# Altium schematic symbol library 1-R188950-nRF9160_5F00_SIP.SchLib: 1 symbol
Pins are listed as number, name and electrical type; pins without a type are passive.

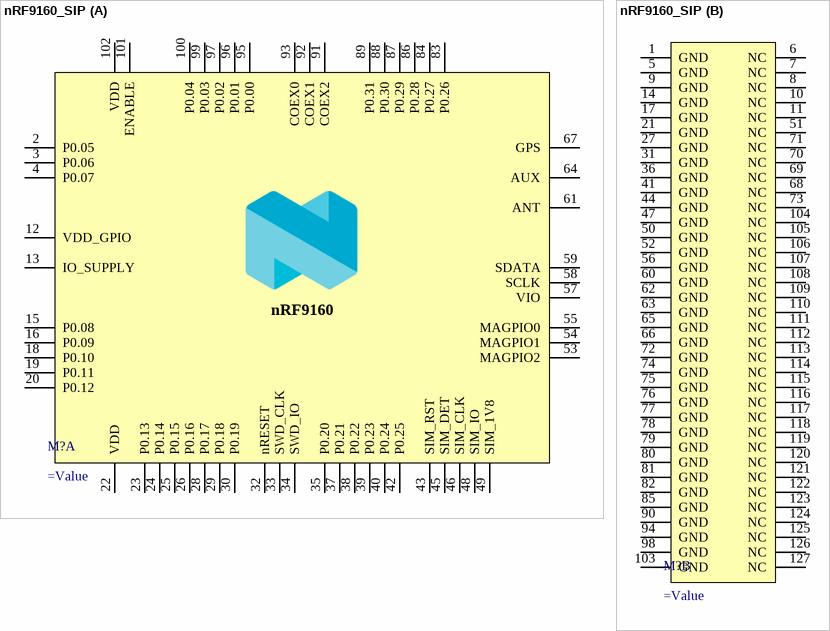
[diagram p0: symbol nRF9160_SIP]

## nRF9160_SIP
designator M?
part A pins: 1 GND hidden to GND, 2 P0.05, 3 P0.06, 4 P0.07, 5 GND hidden to GND, 9 GND hidden to GND, 12 VDD_GPIO, 13 IO_SUPPLY, 14 GND hidden to GND, 15 P0.08, 16 P0.09, 17 GND hidden to GND, 18 P0.10, 19 P0.11, 20 P0.12, 21 GND hidden to GND, 22 VDD, 23 P0.13, 24 P0.14, 25 P0.15, 26 P0.16, 27 GND hidden to GND, 28 P0.17, 29 P0.18, 30 P0.19, 31 GND hidden to GND, 32 nRESET, 33 SWD_CLK, 34 SWD_IO, 35 P0.20, 36 GND hidden to GND, 37 P0.21, 38 P0.22, 39 P0.23, 40 P0.24, 41 GND hidden to GND, 42 P0.25, 43 SIM_RST, 44 GND hidden to GND, 45 SIM_DET, 46 SIM_CLK, 47 GND hidden to GND, 48 SIM_IO, 49 SIM_1V8, 50 GND hidden to GND, 52 GND hidden to GND, 53 MAGPIO2, 54 MAGPIO1, 55 MAGPIO0, 56 GND hidden to GND, 57 VIO, 58 SCLK, 59 SDATA, 60 GND hidden to GND, 61 ANT, 62 GND hidden to GND, 63 GND hidden to GND, 64 AUX, 65 GND hidden to GND, 66 GND hidden to GND, 67 GPS, 72 GND hidden to GND, 74 GND hidden to GND, 75 GND hidden to GND, 76 GND hidden to GND, 77 GND hidden to GND, 78 GND hidden to GND, 79 GND hidden to GND, 80 GND hidden to GND, 81 GND hidden to GND, 82 GND hidden to GND, 83 P0.26, 84 P0.27, 85 GND hidden to GND, 86 P0.28, 87 P0.29, 88 P0.30, 89 P0.31, 90 GND hidden to GND, 91 COEX2, 92 COEX1, 93 COEX0, 94 GND hidden to GND, 95 P0.00, 96 P0.01, 97 P0.02, 98 GND hidden to GND, 99 P0.03, 100 P0.04, 101 ENABLE, 102 VDD, 103 GND hidden to GND
part B pins: 1 GND, 5 GND, 6 NC, 7 NC, 8 NC, 9 GND, 10 NC, 11 NC, 14 GND, 17 GND, 21 GND, 27 GND, 31 GND, 36 GND, 41 GND, 44 GND, 47 GND, 50 GND, 51 NC, 52 GND, 56 GND, 60 GND, 62 GND, 63 GND, 65 GND, 66 GND, 68 NC, 69 NC, 70 NC, 71 NC, 72 GND, 73 NC, 74 GND, 75 GND, 76 GND, 77 GND, 78 GND, 79 GND, 80 GND, 81 GND, 82 GND, 85 GND, 90 GND, 94 GND, 98 GND, 103 GND, 104 NC, 105 NC, 106 NC, 107 NC, 108 NC, 109 NC, 110 NC, 111 NC, 112 NC, 113 NC, 114 NC, 115 NC, 116 NC, 117 NC, 118 NC, 119 NC, 120 NC, 121 NC, 122 NC, 123 NC, 124 NC, 125 NC, 126 NC, 127 NC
